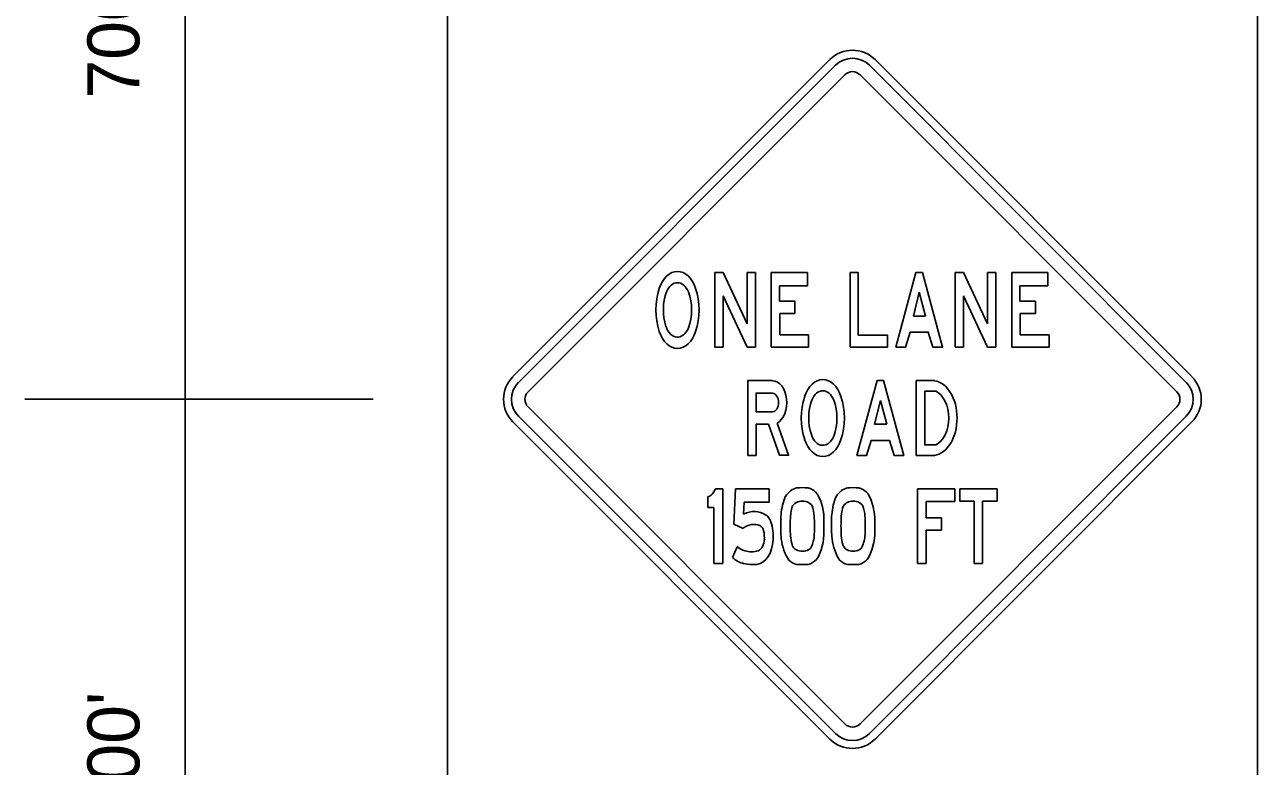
# Model space of a CAD drawing. Extents: x 1531.4 to 1538.6, y 1529.6 to 1539.7.
# Drawn here: x 1536.856 to 1538.277, y 1533.108 to 1533.963 of the extents above; entities that cross this region are included whole.
import ezdxf

# ---------------------------------------------------------------- set-up
doc = ezdxf.new("R2010")
doc.units = 0
for name, color, linetype in [('C-SIGN-FACE-N', 7, 'Continuous'), ('DETL-DIMS', 7, 'Continuous'), ('DETL-LINE', 7, 'Continuous'), ('DETL-NOTE', 7, 'Continuous')]:
    doc.layers.add(name, color=color, linetype=linetype)

msp = doc.modelspace()

# ---------------------------------------------------------------- linework, layer by layer
at = {"layer": 'C-SIGN-FACE-N'}
for p, q in [((1537.784, 1533.9226), (1537.4186, 1533.5573)), ((1538.2015, 1533.5573), (1537.8362, 1533.9226)), ((1537.661, 1533.6772), (1537.6513, 1533.6772)), ((1537.6513, 1533.6772), (1537.6513, 1533.5911)), ((1537.6887, 1533.618), (1537.661, 1533.6772)), ((1537.6984, 1533.6772), (1537.6887, 1533.6772)), ((1537.6887, 1533.6772), (1537.6887, 1533.618)), ((1537.6984, 1533.5911), (1537.6984, 1533.6772)), ((1537.7165, 1533.6772), (1537.7583, 1533.6772)), ((1537.7165, 1533.5911), (1537.7165, 1533.6772)), ((1537.7583, 1533.6772), (1537.7583, 1533.662)), ((1537.8073, 1533.6772), (1537.8167, 1533.6772)), ((1537.8073, 1533.5911), (1537.8073, 1533.6772)), ((1537.8167, 1533.6772), (1537.8167, 1533.6051)), ((1537.9382, 1533.6772), (1537.9285, 1533.6772)), ((1537.9285, 1533.6772), (1537.9285, 1533.5911)), ((1537.9659, 1533.618), (1537.9382, 1533.6772)), ((1537.9756, 1533.6772), (1537.9659, 1533.6772)), ((1537.9659, 1533.6772), (1537.9659, 1533.618)), ((1537.9756, 1533.5911), (1537.9756, 1533.6772)), ((1537.9937, 1533.6772), (1538.0355, 1533.6772)), ((1537.9937, 1533.5911), (1537.9937, 1533.6772)), ((1538.0355, 1533.6772), (1538.0355, 1533.662)), ((1537.7583, 1533.662), (1537.726, 1533.662)), ((1537.726, 1533.662), (1537.726, 1533.6443)), ((1538.0355, 1533.662), (1538.0032, 1533.662)), ((1538.0032, 1533.662), (1538.0032, 1533.6443)), ((1537.661, 1533.5911), (1537.661, 1533.6503)), ((1537.661, 1533.6503), (1537.6887, 1533.5911)), ((1537.726, 1533.6443), (1537.7438, 1533.6443)), ((1537.7438, 1533.6443), (1537.7438, 1533.6299)), ((1537.8805, 1533.627), (1537.8871, 1533.6545)), ((1537.8871, 1533.6545), (1537.8944, 1533.627)), ((1537.9382, 1533.5911), (1537.9382, 1533.6503)), ((1537.9382, 1533.6503), (1537.9659, 1533.5911)), ((1538.0032, 1533.6443), (1538.021, 1533.6443)), ((1538.021, 1533.6443), (1538.021, 1533.6299)), ((1537.7438, 1533.6299), (1537.7263, 1533.6299)), ((1537.7263, 1533.6299), (1537.7263, 1533.6055)), ((1538.021, 1533.6299), (1538.0035, 1533.6299)), ((1538.0035, 1533.6299), (1538.0035, 1533.6055)), ((1537.8944, 1533.627), (1537.8805, 1533.627)), ((1537.7263, 1533.6055), (1537.7596, 1533.6055)), ((1537.7596, 1533.6055), (1537.7596, 1533.5911)), ((1537.8167, 1533.6051), (1537.8504, 1533.6051)), ((1537.8504, 1533.6051), (1537.8504, 1533.5911)), ((1537.8975, 1533.6084), (1537.8976, 1533.6084)), ((1537.8975, 1533.6084), (1537.8976, 1533.6084)), ((1538.0035, 1533.6055), (1538.0368, 1533.6055)), ((1538.0368, 1533.6055), (1538.0368, 1533.5911)), ((1537.6513, 1533.5911), (1537.661, 1533.5911)), ((1537.6887, 1533.5911), (1537.6984, 1533.5911)), ((1537.7596, 1533.5911), (1537.7165, 1533.5911)), ((1537.8504, 1533.5911), (1537.8073, 1533.5911)), ((1537.9285, 1533.5911), (1537.9382, 1533.5911)), ((1537.9659, 1533.5911), (1537.9756, 1533.5911)), ((1538.0368, 1533.5911), (1537.9937, 1533.5911)), ((1537.8357, 1533.5025), (1537.8423, 1533.53)), ((1537.8423, 1533.53), (1537.8496, 1533.5025)), ((1537.784, 1533.1397), (1537.4186, 1533.5051)), ((1537.8496, 1533.5025), (1537.8357, 1533.5025)), ((1538.2015, 1533.5051), (1537.8362, 1533.1397)), ((1537.8527, 1533.4839), (1537.8528, 1533.4839)), ((1537.8527, 1533.4839), (1537.8528, 1533.4839)), ((1537.6432, 1533.4066), (1537.6432, 1533.4187)), ((1537.652, 1533.4281), (1537.6608, 1533.4281)), ((1537.652, 1533.4281), (1537.652, 1533.4281)), ((1537.6608, 1533.4281), (1537.6608, 1533.4281)), ((1537.6608, 1533.4281), (1537.6608, 1533.342)), ((1537.6735, 1533.3874), (1537.6753, 1533.4281)), ((1537.6753, 1533.4281), (1537.7139, 1533.4281)), ((1537.7139, 1533.4281), (1537.7139, 1533.4125)), ((1537.885, 1533.4281), (1537.928, 1533.4281)), ((1537.885, 1533.342), (1537.885, 1533.4281)), ((1537.928, 1533.4281), (1537.928, 1533.4135)), ((1537.9339, 1533.4281), (1537.9769, 1533.4281)), ((1537.9769, 1533.4281), (1537.9339, 1533.4281)), ((1537.9769, 1533.4281), (1537.9339, 1533.4281)), ((1537.9339, 1533.4281), (1537.9339, 1533.4138)), ((1537.9769, 1533.4138), (1537.9769, 1533.4281)), ((1537.6502, 1533.4066), (1537.6432, 1533.4066)), ((1537.6502, 1533.342), (1537.6502, 1533.4066)), ((1537.6852, 1533.4125), (1537.6846, 1533.3989)), ((1537.7139, 1533.4125), (1537.6852, 1533.4125)), ((1537.7454, 1533.4124), (1537.7469, 1533.4129)), ((1537.804, 1533.4124), (1537.8054, 1533.4129)), ((1537.928, 1533.4135), (1537.8949, 1533.4135)), ((1537.8949, 1533.4135), (1537.8949, 1533.3945)), ((1537.9339, 1533.4138), (1537.9506, 1533.4138)), ((1537.9506, 1533.4138), (1537.9506, 1533.342)), ((1537.9602, 1533.342), (1537.9602, 1533.4138)), ((1537.9602, 1533.4138), (1537.9769, 1533.4138)), ((1537.6842, 1533.3825), (1537.6735, 1533.3874)), ((1537.8949, 1533.3945), (1537.9128, 1533.3945)), ((1537.9128, 1533.3945), (1537.9128, 1533.3804)), ((1537.9128, 1533.3804), (1537.8949, 1533.3804)), ((1537.8949, 1533.3804), (1537.8949, 1533.342)), ((1537.6716, 1533.3489), (1537.6771, 1533.3614)), ((1537.6608, 1533.342), (1537.6502, 1533.342)), ((1537.8949, 1533.342), (1537.885, 1533.342)), ((1537.9506, 1533.342), (1537.9602, 1533.342))]:
    msp.add_line(p, q, dxfattribs=at)
for points in [[(1537.7905, 1533.9161), (1537.4252, 1533.5507)], [(1538.195, 1533.5507), (1537.8297, 1533.9161)], [(1537.436, 1533.5399), (1537.8014, 1533.9052)], [(1537.8188, 1533.9052), (1538.1841, 1533.5399)], [(1537.8976, 1533.6084), (1537.8766, 1533.6084), (1537.8713, 1533.5911), (1537.8602, 1533.5911), (1537.8833, 1533.6772), (1537.8908, 1533.6772), (1537.914, 1533.5911), (1537.9029, 1533.5911), (1537.8975, 1533.6084)], [(1537.6894, 1533.4666), (1537.6894, 1533.5527), (1537.6989, 1533.5527), (1537.7179, 1533.5527)], [(1537.8528, 1533.4839), (1537.8318, 1533.4839), (1537.8264, 1533.4666), (1537.8153, 1533.4666), (1537.8385, 1533.5527), (1537.846, 1533.5527), (1537.8692, 1533.4666), (1537.8581, 1533.4666), (1537.8527, 1533.4839)], [(1537.9046, 1533.4666), (1537.8837, 1533.4666), (1537.8837, 1533.5527), (1537.9046, 1533.5527)], [(1537.7179, 1533.5168), (1537.6989, 1533.5168), (1537.6989, 1533.5383), (1537.7179, 1533.5383)], [(1537.9061, 1533.5405), (1537.8934, 1533.5405), (1537.8934, 1533.4787), (1537.9061, 1533.4787)], [(1537.8014, 1533.1571), (1537.436, 1533.5225)], [(1538.1841, 1533.5225), (1537.8188, 1533.1571)], [(1537.4252, 1533.5116), (1537.7905, 1533.1462)], [(1537.7233, 1533.5039), (1537.7365, 1533.4667), (1537.7258, 1533.4667), (1537.7131, 1533.5024), (1537.6989, 1533.5024), (1537.6989, 1533.4666), (1537.6894, 1533.4666)], [(1537.8297, 1533.1462), (1538.195, 1533.5116)]]:
    msp.add_lwpolyline(points, dxfattribs=at)
for centre, radius, start, end in [((1537.8101, 1533.8965), 0.0369, 45, 135), ((1537.8101, 1533.8965), 0.0277, 45, 135), ((1537.8101, 1533.8965), 0.0123, 45, 135), ((1537.4447, 1533.5312), 0.0369, 135, 225), ((1538.1754, 1533.5312), 0.0369, 315, 45), ((1537.4447, 1533.5312), 0.0277, 135, 225), ((1538.1754, 1533.5312), 0.0277, 315, 45), ((1537.4447, 1533.5312), 0.0123, 135, 225), ((1538.1754, 1533.5312), 0.0123, 315, 45), ((1537.8101, 1533.1658), 0.0277, 225, 315), ((1537.8101, 1533.1658), 0.0123, 225, 315), ((1537.8101, 1533.1658), 0.0369, 225, 315)]:
    msp.add_arc(centre, radius, start, end, dxfattribs=at)
for centre, major_axis, ratio, start_param, end_param in [((1537.6083, 1533.6437), (0, 0.0349), 0.667963, 5.167056, 7.399315), ((1537.6201, 1533.6342), (0, 0.0549), 0.667963, 1.101522, 2.04007), ((1537.6083, 1533.6437), (0, 0.0219), 0.667963, 5.251232, 7.315139), ((1537.5965, 1533.6342), (0, 0.0549), 0.667963, 4.243115, 5.181663), ((1537.6201, 1533.6342), (0, 0.042), 0.667963, 1.053076, 2.040122), ((1537.5965, 1533.6342), (0, 0.042), 0.667963, 4.194619, 5.230159), ((1537.6083, 1533.6247), (0, 0.0219), 0.667963, 2.025521, 4.173604), ((1537.6083, 1533.6247), (0, 0.0349), 0.667963, 2.025463, 4.257722), ((1537.7177, 1533.5275), (0, 0.0251), 0.661997, 3.487455, 6.26934), ((1537.7759, 1533.5191), (0, 0.0349), 0.667963, 5.167056, 7.399315), ((1537.902, 1533.5096), (0, 0.0432), 0.666086, 3.232672, 6.192106), ((1537.7177, 1533.5275), (0, 0.0108), 0.661997, 3.174143, 6.250635), ((1537.7877, 1533.5096), (0, 0.0549), 0.667963, 1.101522, 2.04007), ((1537.7877, 1533.5096), (0, 0.042), 0.667963, 1.053076, 2.040122), ((1537.7759, 1533.5191), (0, 0.0219), 0.667963, 5.251232, 7.315139), ((1537.7641, 1533.5096), (0, 0.042), 0.667963, 4.194619, 5.230159), ((1537.7641, 1533.5096), (0, 0.0549), 0.667963, 4.243115, 5.181663), ((1537.8996, 1533.5096), (0, 0.0324), 0.666086, 3.446507, 5.978271), ((1537.7759, 1533.5001), (0, 0.0219), 0.667963, 2.025521, 4.173604), ((1537.7759, 1533.5001), (0, 0.0349), 0.667963, 2.025463, 4.257722), ((1537.749, 1533.3961), (0, 0.0334), 0.673292, 0.14892, 0.810922), ((1537.7523, 1533.266), (0, 0.1634), 0.673292, 6.222514, 6.343857), ((1537.7557, 1533.3961), (0, 0.0334), 0.673292, 5.722299, 6.134265), ((1537.8075, 1533.3961), (0, 0.0334), 0.673292, 0.14892, 0.810922), ((1537.8109, 1533.266), (0, 0.1634), 0.673292, 6.222514, 6.343857), ((1537.8142, 1533.3961), (0, 0.0334), 0.673292, 5.722299, 6.134265), ((1537.6408, 1533.4385), (0, 0.0201), 0.650778, 3.332111, 4.172526), ((1537.7626, 1533.3917), (0, 0.0522), 0.673292, 1.018107, 1.445264), ((1537.7523, 1533.3815), (0, 0.0325), 0.673292, 5.951597, 6.603903), ((1537.7641, 1533.4153), (0, 0.0104), 0.673292, 5.381528, 5.762553), ((1537.7471, 1533.3922), (0, 0.0448), 0.673292, 4.670405, 5.436556), ((1537.8211, 1533.3917), (0, 0.0522), 0.673292, 1.018107, 1.445264), ((1537.8109, 1533.3815), (0, 0.0325), 0.673292, 5.951597, 6.603903), ((1537.8227, 1533.4153), (0, 0.0104), 0.673292, 5.381528, 5.762553), ((1537.8056, 1533.3922), (0, 0.0448), 0.673292, 4.670405, 5.436556), ((1537.6965, 1533.3478), (0, 0.0541), 0.677072, 5.895147, 6.613614), ((1537.7642, 1533.3917), (0, 0.0382), 0.673292, 1.113599, 1.448798), ((1537.749, 1533.3961), (0, 0.0171), 0.673292, 0.185197, 0.757154), ((1537.7557, 1533.3961), (0, 0.0171), 0.673292, 5.526031, 6.097989), ((1537.7405, 1533.3917), (0, 0.0382), 0.673292, 4.834387, 5.169586), ((1537.8227, 1533.3917), (0, 0.0382), 0.673292, 1.113599, 1.448798), ((1537.8075, 1533.3961), (0, 0.0171), 0.673292, 0.185197, 0.757154), ((1537.8142, 1533.3961), (0, 0.0171), 0.673292, 5.526031, 6.097989), ((1537.799, 1533.3917), (0, 0.0382), 0.673292, 4.834387, 5.169586), ((1537.6965, 1533.3478), (0, 0.0392), 0.677072, 6.021739, 6.764061), ((1537.7014, 1533.3758), (0, 0.0102), 0.677072, 4.86848, 6.007028), ((1537.7057, 1533.3825), (0, 0.0169), 0.677072, 5.195666, 5.862161), ((1537.7006, 1533.3761), (0, 0.0265), 0.677072, 4.84619, 5.276323), ((1537.8556, 1533.3851), (0, 0.1904), 0.673292, 1.501071, 1.600681), ((1537.8556, 1533.3851), (0, 0.1741), 0.673292, 1.501071, 1.640521), ((1537.649, 1533.3851), (0, 0.1741), 0.673292, 4.642664, 4.782114), ((1537.7405, 1533.3917), (0, 0.0545), 0.673292, 4.834387, 4.840668), ((1537.649, 1533.3851), (0, 0.1904), 0.673292, 4.68488, 4.739898), ((1537.9141, 1533.3851), (0, 0.1904), 0.673292, 1.501071, 1.600681), ((1537.9141, 1533.3851), (0, 0.1741), 0.673292, 1.501071, 1.640521), ((1537.7076, 1533.3851), (0, 0.1741), 0.673292, 4.642664, 4.782114), ((1537.799, 1533.3917), (0, 0.0545), 0.673292, 4.834387, 4.840668), ((1537.7076, 1533.3851), (0, 0.1904), 0.673292, 4.68488, 4.739898), ((1537.6852, 1533.3724), (0, 0.0344), 0.677072, 4.643864, 4.857063), ((1537.6919, 1533.3736), (0, 0.0396), 0.677072, 4.606968, 4.8659), ((1537.772, 1533.3818), (0, 0.0662), 0.673292, 1.587013, 1.741903), ((1537.7642, 1533.3784), (0, 0.0382), 0.673292, 1.692795, 1.959788), ((1537.7471, 1533.3779), (0, 0.0284), 0.673292, 3.99744, 4.562115), ((1537.7405, 1533.3784), (0, 0.0382), 0.673292, 4.587871, 4.590391), ((1537.7471, 1533.3779), (0, 0.0448), 0.673292, 3.941978, 4.754373), ((1537.7405, 1533.3784), (0, 0.0545), 0.673292, 4.584109, 4.590391), ((1537.8306, 1533.3818), (0, 0.0662), 0.673292, 1.587013, 1.741903), ((1537.8227, 1533.3784), (0, 0.0382), 0.673292, 1.692795, 1.959788), ((1537.8056, 1533.3779), (0, 0.0284), 0.673292, 3.99744, 4.562115), ((1537.799, 1533.3784), (0, 0.0382), 0.673292, 4.587871, 4.590391), ((1537.8056, 1533.3779), (0, 0.0448), 0.673292, 3.941978, 4.754373), ((1537.799, 1533.3784), (0, 0.0545), 0.673292, 4.584109, 4.590391), ((1537.6914, 1533.3991), (0, 0.0431), 0.677072, 2.63257, 2.96212), ((1537.6983, 1533.3709), (0, 0.03), 0.677072, 3.219888, 4.662678), ((1537.6983, 1533.3709), (0, 0.0151), 0.677072, 3.460339, 4.655582), ((1537.7578, 1533.3779), (0, 0.0448), 0.673292, 1.737637, 2.364749), ((1537.747, 1533.3685), (0, 0.0109), 0.673292, 1.88811, 2.52004), ((1537.749, 1533.374), (0, 0.0171), 0.673292, 2.570329, 2.825982), ((1537.7523, 1533.3886), (0, 0.0325), 0.673292, 2.820875, 3.473181), ((1537.7557, 1533.374), (0, 0.0171), 0.673292, 3.326789, 3.676893), ((1537.8164, 1533.3779), (0, 0.0448), 0.673292, 1.737637, 2.364749), ((1537.8056, 1533.3685), (0, 0.0109), 0.673292, 1.88811, 2.52004), ((1537.8075, 1533.374), (0, 0.0171), 0.673292, 2.570329, 2.825982), ((1537.8109, 1533.3886), (0, 0.0325), 0.673292, 2.820875, 3.473181), ((1537.8142, 1533.374), (0, 0.0171), 0.673292, 3.326789, 3.676893), ((1537.6914, 1533.3991), (0, 0.0581), 0.677072, 2.615372, 2.978865), ((1537.6939, 1533.4168), (0, 0.0613), 0.677072, 2.953777, 3.324735), ((1537.749, 1533.374), (0, 0.0334), 0.673292, 2.563158, 2.992672), ((1537.7557, 1533.374), (0, 0.0334), 0.673292, 3.290513, 3.759768), ((1537.8075, 1533.374), (0, 0.0334), 0.673292, 2.563158, 2.992672), ((1537.8142, 1533.374), (0, 0.0334), 0.673292, 3.290513, 3.759768), ((1537.6946, 1533.4303), (0, 0.0896), 0.677072, 2.98267, 3.228038), ((1537.7523, 1533.5041), (0, 0.1634), 0.673292, 3.080921, 3.202264), ((1537.8109, 1533.5041), (0, 0.1634), 0.673292, 3.080921, 3.202264)]:
    msp.add_ellipse(centre, major_axis=major_axis, ratio=ratio, start_param=start_param, end_param=end_param, dxfattribs=at)
at = {"layer": 'DETL-DIMS'}
for p, q in [((1537.0405, 1534.4286), (1537.0405, 1533.5312)), ((1537.2575, 1533.5312), (1536.8556, 1533.5312)), ((1537.0405, 1533.5312), (1537.0405, 1532.6884))]:
    msp.add_line(p, q, dxfattribs=at)
at = {"layer": 'DETL-LINE'}
msp.add_lwpolyline([(1537.3432, 1535.2018), (1538.277, 1535.2018), (1538.277, 1532.2226), (1537.3432, 1532.2226)], close=True, dxfattribs=at)

# ---------------------------------------------------------------- texts
at = {"layer": 'DETL-NOTE'}
for s, p in [("700'", (1536.9879, 1533.8778)), ("1100'", (1536.9879, 1533.0004))]:
    msp.add_text(s, height=0.06, rotation=90, dxfattribs=at).set_placement(p)

doc.saveas('drawing.dxf')
